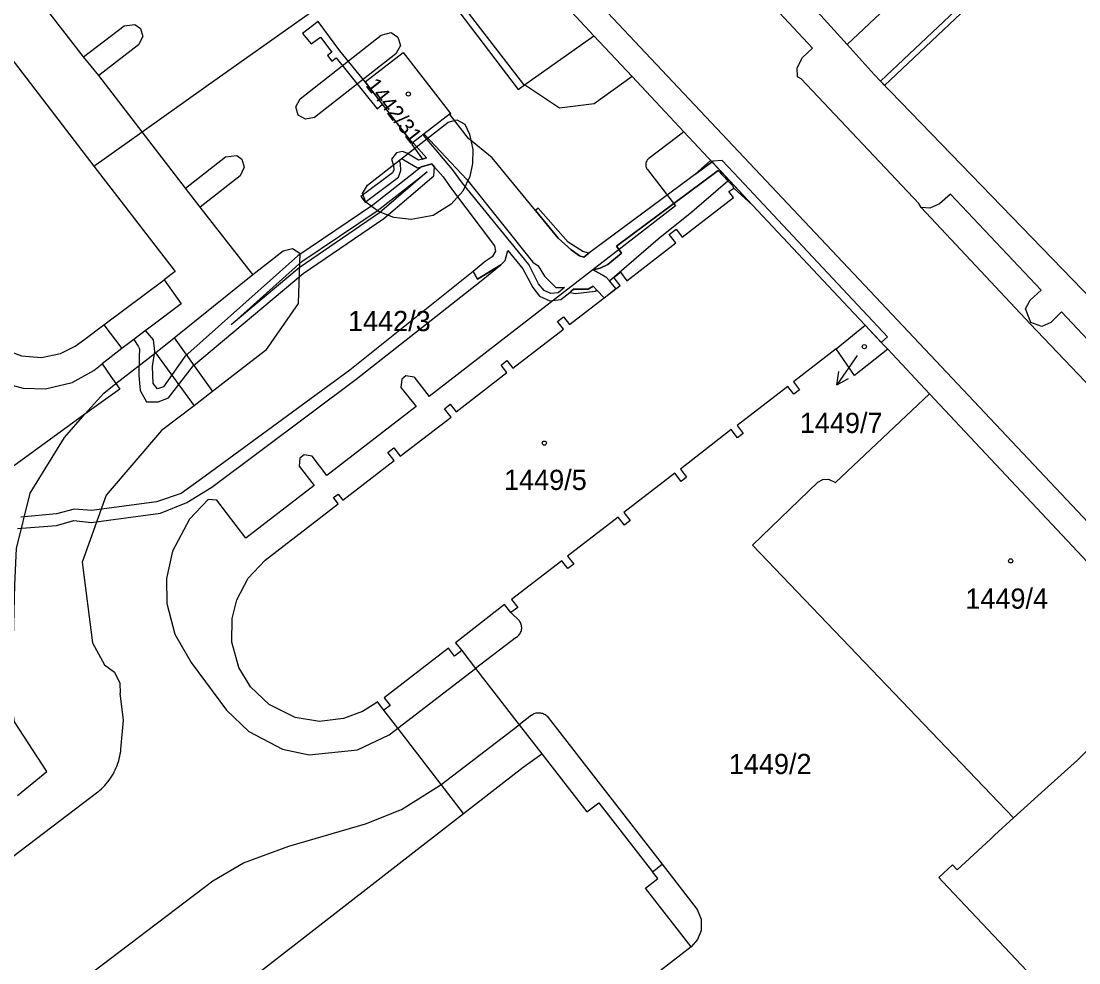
# Model space of a CAD drawing. Extents: x -821458 to -820266, y -1071458 to -1069826.
# Drawn here: x -821357.4 to -821268.4, y -1070486.3 to -1070407.2 of the extents above; entities that cross this region are included whole.
import ezdxf

# ---------------------------------------------------------------- set-up
doc = ezdxf.new("R2010")
doc.units = 0
for name, color, linetype in [('Vrstva 1', 7, 'Continuous'), ('Vrstva 13', 7, 'Continuous'), ('Vrstva 2', 7, 'Continuous'), ('Vrstva 4', 7, 'Continuous'), ('Vrstva 5', 7, 'Continuous'), ('Vrstva 7', 7, 'Continuous')]:
    doc.layers.add(name, color=color, linetype=linetype)

msp = doc.modelspace()

# ---------------------------------------------------------------- linework, layer by layer
at = {"layer": 'Vrstva 1'}
for p, q in [((-821293.71, -1070402.72), (-821287.92, -1070409.14)), ((-821288.83, -1070434.71), (-821286.39, -1070432.73)), ((-821280.98, -1070438.5), (-821284.5, -1070434.75)), ((-821260.09, -1070460.79), (-821280.98, -1070438.5))]:
    msp.add_line(p, q, dxfattribs=at)
for points in [[(-821309.21, -1070408.41), (-821319.78, -1070397.04), (-821333.24, -1070382.81), (-821356.7, -1070357.89), (-821358.08, -1070356.41), (-821363.03, -1070351.13), (-821378.93, -1070334.19)], [(-821285.11, -1070412.22), (-821269.17, -1070397.16), (-821271.43, -1070394.76)], [(-821272.9, -1070394.94), (-821276.13, -1070398.02), (-821276.59, -1070398.45), (-821278.3, -1070400.08), (-821278.45, -1070400.22), (-821284.67, -1070406.08), (-821287.92, -1070409.14)], [(-821351.25, -1070419.35), (-821347.19, -1070416.48), (-821341.82, -1070412.67), (-821325.37, -1070401), (-821323.53, -1070403.59), (-821322.96, -1070403.16), (-821315.57, -1070412.92), (-821315.04, -1070412.54), (-821309.21, -1070408.41)], [(-821360.92, -1070406.79), (-821351.25, -1070419.35)], [(-821295.86, -1070422.64), (-821301.64, -1070416.48), (-821305.99, -1070411.84), (-821309.21, -1070408.41)], [(-821328.45, -1070412.27), (-821325.25, -1070409.8), (-821321.27, -1070414.93), (-821324.45, -1070417.4), (-821328.45, -1070412.27)], [(-821287.92, -1070409.14), (-821285.64, -1070411.67), (-821285.11, -1070412.22)], [(-821183.73, -1070520.92), (-821205.46, -1070496.83), (-821215, -1070486.68), (-821216.61, -1070484.97), (-821257.56, -1070440.79), (-821261.33, -1070436.77), (-821285.11, -1070412.22)], [(-821394.98, -1070419.44), (-821390.24, -1070415.79), (-821375.82, -1070417.64), (-821362.5, -1070434.98), (-821361.14, -1070436.34), (-821359.22, -1070437.48), (-821357.18, -1070438.02), (-821355.31, -1070438.07), (-821353.07, -1070437.54), (-821351.25, -1070436.53), (-821350.55, -1070435.98)], [(-821350.55, -1070435.98), (-821349.81, -1070437.03), (-821349.39, -1070437.64), (-821349.07, -1070438.1), (-821352, -1070440.22), (-821360.71, -1070446.53), (-821360.94, -1070446.7), (-821361.48, -1070447.09), (-821368.87, -1070452.45), (-821370.62, -1070453.72), (-821370.9, -1070453.92), (-821370.95, -1070453.85), (-821375.3, -1070447.61), (-821390.16, -1070426.35), (-821392.14, -1070423.51), (-821394.98, -1070419.44)], [(-821351.25, -1070419.35), (-821344.42, -1070428.21), (-821345.35, -1070428.92), (-821343.92, -1070430.93), (-821348.9, -1070434.69), (-821350.55, -1070435.98)], [(-821326.86, -1070465.1), (-821327.39, -1070464.39), (-821327.53, -1070464.5), (-821328.67, -1070465.21), (-821330.25, -1070465.8), (-821332.28, -1070466.03), (-821334.32, -1070465.69), (-821336.5, -1070464.62), (-821338.07, -1070463.13), (-821339.05, -1070461.51), (-821339.64, -1070459.37), (-821339.62, -1070457.39), (-821339.24, -1070455.8), (-821338.28, -1070453.99), (-821336.85, -1070452.48), (-821330.71, -1070447.74), (-821331.11, -1070447.22), (-821330.71, -1070446.92), (-821330.31, -1070447.44), (-821326.01, -1070444.11), (-821326.53, -1070443.43), (-821326.02, -1070443.04), (-821325.49, -1070443.73), (-821321.22, -1070440.45), (-821321.76, -1070439.75), (-821321.28, -1070439.37), (-821320.78, -1070440.01), (-821316.52, -1070436.72), (-821317.01, -1070436.08), (-821316.52, -1070435.7), (-821316.03, -1070436.34), (-821311.76, -1070433.06), (-821312.26, -1070432.41), (-821311.76, -1070432.02), (-821311.25, -1070432.68), (-821307, -1070429.38), (-821307.52, -1070428.71), (-821306.98, -1070428.28), (-821306.43, -1070429), (-821302.32, -1070425.82), (-821302.87, -1070425.1), (-821302.28, -1070424.66), (-821301.77, -1070425.32), (-821297.46, -1070422), (-821297.85, -1070421.49), (-821297.44, -1070421.22), (-821295.86, -1070422.64)], [(-821286.39, -1070432.73), (-821287.8, -1070431.23), (-821295.86, -1070422.64)], [(-821284.5, -1070434.75), (-821284.77, -1070434.47), (-821286.39, -1070432.73)], [(-821288.83, -1070434.71), (-821292.43, -1070437.48), (-821291.91, -1070438.16), (-821292.39, -1070438.54), (-821292.91, -1070437.87), (-821297.17, -1070441.15), (-821296.65, -1070441.83), (-821297.13, -1070442.2), (-821297.66, -1070441.51), (-821301.93, -1070444.82), (-821301.41, -1070445.49), (-821301.88, -1070445.86), (-821302.41, -1070445.18), (-821306.68, -1070448.48), (-821306.16, -1070449.15), (-821306.64, -1070449.54), (-821307.17, -1070448.86), (-821311.42, -1070452.15), (-821310.9, -1070452.82), (-821311.39, -1070453.18), (-821311.89, -1070452.53), (-821316.12, -1070455.79), (-821315.61, -1070456.46), (-821316.2, -1070456.88), (-821316.72, -1070456.21), (-821320.83, -1070459.42), (-821320.32, -1070460.08), (-821320.92, -1070460.54), (-821321.44, -1070459.87), (-821326.83, -1070464.06), (-821326.33, -1070464.7), (-821326.86, -1070465.1)], [(-821284.5, -1070434.75), (-821287.28, -1070436.95), (-821288.83, -1070434.71)], [(-821273.93, -1070474.15), (-821295.87, -1070451.21), (-821290.38, -1070445.93), (-821289.95, -1070445.7), (-821289.47, -1070445.67), (-821288.88, -1070445.96), (-821280.98, -1070438.5)], [(-821260.09, -1070460.79), (-821268.54, -1070469.28), (-821271.57, -1070472.02), (-821273.93, -1070474.15)], [(-821320.16, -1070473.76), (-821322.04, -1070471.33), (-821325.7, -1070466.6), (-821326.86, -1070465.1)], [(-821320.16, -1070473.76), (-821315.16, -1070469.88), (-821313.58, -1070468.77), (-821309.79, -1070473.64), (-821308.8, -1070472.89), (-821304.29, -1070478.67), (-821303.47, -1070478.04), (-821300.52, -1070481.83), (-821300.18, -1070482.66), (-821300.19, -1070483.6), (-821300.49, -1070484.36), (-821301.04, -1070484.97), (-821304.49, -1070487.68), (-821307.43, -1070489.92), (-821331.64, -1070508.76), (-821336.37, -1070512.34), (-821340.055, -1070515.253)], [(-821351.742, -1070498.854), (-821351.38, -1070498.3), (-821349.56, -1070496.61), (-821343.56, -1070491.95), (-821320.16, -1070473.76)], [(-821273.93, -1070474.15), (-821275.52, -1070475.59), (-821275.85, -1070475.93), (-821278.67, -1070478.52), (-821279.06, -1070478.09), (-821280.19, -1070479.14), (-821279.86, -1070479.52), (-821275.13, -1070484.54), (-821270.46, -1070489.5), (-821261.8, -1070481.24)]]:
    msp.add_lwpolyline(points, dxfattribs=at)
at = {"layer": 'Vrstva 13'}
for points in [[(-821285.11, -1070412.22), (-821284.76, -1070412.58), (-821268.47, -1070397.18), (-821271.68, -1070393.78), (-821272.04, -1070394.12), (-821269.17, -1070397.16)], [(-821326.99, -1070414.14), (-821328.45, -1070412.27), (-821330.58, -1070409.67), (-821332.4, -1070407.19), (-821333.72, -1070408.2), (-821332.98, -1070409.07), (-821332.18, -1070408.51), (-821331.24, -1070409.79), (-821331.61, -1070410.07), (-821331.25, -1070410.55), (-821330.87, -1070410.27), (-821327.44, -1070414.54)], [(-821321.23, -1070414.98), (-821321.27, -1070414.93), (-821324.45, -1070417.4), (-821328.45, -1070412.27), (-821324.45, -1070417.48), (-821324.37, -1070417.42), (-821323.27, -1070418.67), (-821323.62, -1070418.77), (-821323.96, -1070418.87), (-821324.94, -1070418.28), (-821325.3, -1070418.13), (-821325.81, -1070418.25), (-821326.22, -1070418.78), (-821326.06, -1070419.3), (-821326.03, -1070419.66), (-821326.13, -1070419.91), (-821328.8, -1070421.92), (-821328.44, -1070422.4), (-821325.63, -1070420.29), (-821325.43, -1070419.74), (-821325.46, -1070419.18), (-821325.56, -1070418.9), (-821325.47, -1070418.79), (-821325.35, -1070418.76), (-821325.2, -1070418.82), (-821324.04, -1070419.51), (-821323.69, -1070419.41), (-821322.83, -1070419.17), (-821322.6, -1070419.44), (-821321.87, -1070420.27), (-821321.18, -1070421.27), (-821317.55, -1070426.05), (-821317.48, -1070426.51), (-821317.77, -1070426.98), (-821318.34, -1070427.37), (-821319.37, -1070428.22), (-821318.98, -1070428.86), (-821318.06, -1070428.31), (-821317.03, -1070427.67), (-821316.66, -1070427.28), (-821316.43, -1070426.44), (-821315.18, -1070427.98), (-821314.35, -1070429.57), (-821313.77, -1070430.3), (-821312.92, -1070430.69), (-821311.98, -1070430.58), (-821311.22, -1070429.97), (-821311.11, -1070429.88), (-821310.91, -1070429.69), (-821309.69, -1070429.7), (-821309.28, -1070429.46), (-821308.97, -1070429.78), (-821308.34, -1070430.42), (-821307.35, -1070429.65), (-821307.9, -1070429.01), (-821308.17, -1070428.68), (-821309.28, -1070428.07), (-821308.68, -1070427.94), (-821308.02, -1070427.62), (-821306.88, -1070426.68), (-821307.31, -1070426.1), (-821298.77, -1070419.73), (-821297.59, -1070420.97), (-821297.44, -1070421.22), (-821295.86, -1070422.64), (-821299.27, -1070419.01), (-821299.58, -1070419.21), (-821309.09, -1070426.27), (-821309.62, -1070426.68), (-821310.06, -1070427.02), (-821310.42, -1070426.9), (-821311.13, -1070426.4), (-821312.2, -1070425.42), (-821314.11, -1070423.1), (-821317.75, -1070418.65), (-821319.74, -1070417.03), (-821321.3, -1070415.04)], [(-821314.33, -1070427.44), (-821313.88, -1070427.73), (-821313.35, -1070428.61), (-821312.4, -1070429.57), (-821311.69, -1070429.57), (-821312.22, -1070430), (-821312.82, -1070430.07), (-821313.39, -1070429.82), (-821313.85, -1070429.25), (-821314.68, -1070427.64), (-821320.25, -1070420.78), (-821321.09, -1070419.64), (-821323.52, -1070416.76), (-821323.44, -1070416.7), (-821319.9, -1070420.49)], [(-821324.37, -1070417.42), (-821324.45, -1070417.48), (-821324.52, -1070417.53), (-821323.62, -1070418.77), (-821323.27, -1070418.67)], [(-821299.27, -1070419.01), (-821299.39, -1070418.88), (-821300.72, -1070420.06), (-821299.58, -1070419.21)], [(-821299.27, -1070419.01), (-821295.86, -1070422.64), (-821287.8, -1070431.23), (-821286.39, -1070432.73), (-821285.04, -1070434.18), (-821284.52, -1070433.7), (-821292.48, -1070425.21), (-821296.98, -1070420.41), (-821298.42, -1070418.89), (-821299.18, -1070418.95)], [(-821345.38, -1070437.9), (-821345.91, -1070438.09), (-821346.26, -1070437.63), (-821346.32, -1070436.2), (-821346.12, -1070434.94), (-821346.23, -1070433.97), (-821346.9, -1070433.18), (-821347.89, -1070433.93), (-821347.52, -1070434.49), (-821347.42, -1070434.73), (-821347.43, -1070435.36), (-821347.47, -1070436.95), (-821347.35, -1070438.23), (-821346.81, -1070439.17), (-821345.84, -1070439.17), (-821344.98, -1070438.83), (-821342.87, -1070436.13), (-821333.64, -1070428.39), (-821326.87, -1070423.77), (-821322.65, -1070420.17), (-821322.6, -1070419.44), (-821322.83, -1070419.17), (-821323.69, -1070419.41), (-821327.79, -1070422.64), (-821334.11, -1070426.89), (-821343.61, -1070435.37)], [(-821309.28, -1070428.07), (-821308.17, -1070428.68), (-821307.9, -1070429.01), (-821303.81, -1070425.46), (-821300.96, -1070423.2), (-821297.95, -1070420.59), (-821298.77, -1070419.73), (-821307.31, -1070426.1), (-821306.88, -1070426.68), (-821308.02, -1070427.62), (-821308.68, -1070427.94)], [(-821327.23, -1070423.29), (-821334, -1070427.91), (-821339.71, -1070432.69), (-821333.75, -1070427.37), (-821327.43, -1070423.12), (-821323.23, -1070419.85)], [(-821310.06, -1070427.02), (-821309.62, -1070426.68), (-821310.14, -1070426.54), (-821311.36, -1070425.76), (-821313.89, -1070422.88), (-821314.11, -1070423.1), (-821312.2, -1070425.42), (-821311.13, -1070426.4), (-821310.42, -1070426.9)], [(-821311.22, -1070429.97), (-821310.74, -1070430.06), (-821309.1, -1070429.87), (-821308.97, -1070429.78), (-821309.28, -1070429.46), (-821309.69, -1070429.7), (-821310.91, -1070429.69), (-821311.11, -1070429.88)]]:
    msp.add_lwpolyline(points, close=True, dxfattribs=at)
msp.add_lwpolyline([(-821357.66, -1070449.83), (-821354.4, -1070449.56), (-821352.92, -1070449.15), (-821351.47, -1070449.3), (-821345.64, -1070448.52), (-821343.44, -1070447.63), (-821341.32, -1070446.34), (-821329.2, -1070437.28), (-821318.67, -1070428.99), (-821317.03, -1070427.67), (-821318.98, -1070428.86), (-821319.37, -1070428.22), (-821329.74, -1070436.52), (-821341.88, -1070445.41), (-821343.91, -1070446.89), (-821345.97, -1070447.57), (-821351.41, -1070448.3), (-821352.9, -1070448.18), (-821354.4, -1070448.59), (-821357.39, -1070448.86)], dxfattribs=at)
at = {"layer": 'Vrstva 4'}
for p, q in [((-821352.11, -1070410.18), (-821359.45, -1070400.69)), ((-821290.82, -1070409.44), (-821298.28, -1070401.44)), ((-821350.84, -1070411.75), (-821352.11, -1070410.18)), ((-821347.19, -1070416.48), (-821350.84, -1070411.75)), ((-821343.54, -1070421.2), (-821347.19, -1070416.48)), ((-821302.25, -1070416.94), (-821304.59, -1070418.72)), ((-821301.64, -1070416.48), (-821302.25, -1070416.94)), ((-821304.71, -1070419.64), (-821302.35, -1070422.7)), ((-821342.3, -1070422.8), (-821343.54, -1070421.2)), ((-821337.88, -1070428.47), (-821342.3, -1070422.8)), ((-821302.35, -1070422.7), (-821323.07, -1070438.73)), ((-821344.5, -1070433.8), (-821337.88, -1070428.47)), ((-821350.41, -1070432.69), (-821345.35, -1070428.92)), ((-821352.02, -1070433.9), (-821350.41, -1070432.69)), ((-821350.41, -1070432.69), (-821348.9, -1070434.69)), ((-821346.06, -1070435.06), (-821344.5, -1070433.8)), ((-821344.5, -1070433.8), (-821341.26, -1070438.29)), ((-821349.39, -1070437.64), (-821346.06, -1070435.06)), ((-821346.06, -1070435.06), (-821342.82, -1070439.52)), ((-821325.36, -1070437.28), (-821325.43, -1070437.96)), ((-821325.01, -1070437), (-821325.36, -1070437.28)), ((-821324.32, -1070437.1), (-821325.01, -1070437)), ((-821324.32, -1070437.1), (-821323.07, -1070438.73)), ((-821341.26, -1070438.29), (-821342.82, -1070439.52)), ((-821325.43, -1070437.96), (-821324.15, -1070439.55)), ((-821324.15, -1070439.55), (-821331.66, -1070445.37)), ((-821333.56, -1070443.63), (-821333.92, -1070443.9)), ((-821332.9, -1070443.75), (-821333.56, -1070443.63)), ((-821331.66, -1070445.37), (-821332.9, -1070443.75)), ((-821333.92, -1070443.9), (-821334, -1070444.58)), ((-821334, -1070444.58), (-821332.73, -1070446.19)), ((-821332.73, -1070446.19), (-821338.47, -1070450.63)), ((-821341.63, -1070447.38), (-821343.21, -1070449.04)), ((-821340.92, -1070447.44), (-821341.63, -1070447.38)), ((-821338.47, -1070450.63), (-821340.92, -1070447.44)), ((-821343.21, -1070449.04), (-821344.64, -1070451.71)), ((-821344.64, -1070451.71), (-821345.14, -1070454.01)), ((-821345.14, -1070454.01), (-821345.12, -1070456.13)), ((-821345.12, -1070456.13), (-821344.45, -1070458.71)), ((-821315.47, -1070457.57), (-821316.2, -1070456.88)), ((-821344.45, -1070458.71), (-821343.07, -1070461.07)), ((-821351.36, -1070459.44), (-821350.36, -1070461.28)), ((-821315.7, -1070458.95), (-821319.15, -1070461.59)), ((-821320.32, -1070460.08), (-821319.15, -1070461.59)), ((-821343.07, -1070461.07), (-821340.1, -1070465.08)), ((-821325.7, -1070466.6), (-821319.15, -1070461.59)), ((-821319.15, -1070461.59), (-821315.49, -1070466.31)), ((-821348.76, -1070465.92), (-821349.05, -1070463.65)), ((-821340.1, -1070465.08), (-821338.23, -1070466.88)), ((-821348.97, -1070468.37), (-821348.76, -1070465.92)), ((-821314.44, -1070465.5), (-821315.49, -1070466.31)), ((-821313.05, -1070465.69), (-821303.47, -1070478.04)), ((-821338.23, -1070466.88), (-821335.38, -1070468.37)), ((-821326.42, -1070467.15), (-821325.7, -1070466.6)), ((-821322.04, -1070471.33), (-821315.49, -1070466.31)), ((-821315.49, -1070466.31), (-821313.58, -1070468.77)), ((-821329.09, -1070468.43), (-821326.42, -1070467.15)), ((-821335.38, -1070468.37), (-821333.15, -1070468.85)), ((-821333.15, -1070468.85), (-821329.09, -1070468.43)), ((-821322.21, -1070471.46), (-821322.04, -1070471.33)), ((-821350.92, -1070471.97), (-821361.45, -1070479.98)), ((-821325.37, -1070473.44), (-821322.21, -1070471.46)), ((-821328.4, -1070474.65), (-821325.37, -1070473.44)), ((-821334.86, -1070476.52), (-821328.4, -1070474.65)), ((-821338.66, -1070477.92), (-821334.86, -1070476.52)), ((-821341.25, -1070479.44), (-821338.66, -1070477.92)), ((-821304.86, -1070480.04), (-821303.84, -1070479.25)), ((-821303.84, -1070479.25), (-821304.29, -1070478.67)), ((-821354.34, -1070489.34), (-821341.25, -1070479.44)), ((-821301.04, -1070484.97), (-821304.86, -1070480.04))]:
    msp.add_line(p, q, dxfattribs=at)
for points in [[(-821354.82, -1070356.72), (-821348.41, -1070363.52), (-821328.79, -1070384.4), (-821304.41, -1070410.3), (-821282.75, -1070433.29), (-821254.81, -1070462.93)], [(-821315.04, -1070412.54), (-821315.09, -1070412.51), (-821357.05, -1070358.16), (-821356.7, -1070357.89)], [(-821352.11, -1070410.18), (-821348.71, -1070407.57), (-821347.79, -1070407.45), (-821347.33, -1070407.79), (-821347.13, -1070408.47), (-821347.5, -1070409.17), (-821350.84, -1070411.75)], [(-821333.89, -1070413.7), (-821327.09, -1070408.34), (-821326.26, -1070408.14), (-821325.68, -1070408.52), (-821325.48, -1070409.22), (-821325.85, -1070409.91), (-821332.69, -1070415.26), (-821333.45, -1070415.42), (-821334.06, -1070415.07), (-821334.26, -1070414.37), (-821333.89, -1070413.7)], [(-821292.11, -1070411.1), (-821291.67, -1070410.24), (-821290.82, -1070409.44)], [(-821281.7, -1070422.85), (-821281.88, -1070422.51), (-821291.78, -1070412.03), (-821292.08, -1070411.85), (-821292.11, -1070411.1)], [(-821305.99, -1070411.84), (-821309.18, -1070414.12), (-821312.11, -1070414.49), (-821315.04, -1070412.54)], [(-821396.41, -1070417.4), (-821391.83, -1070413.88), (-821373.58, -1070416.24), (-821360.52, -1070433.51), (-821358.97, -1070434.7), (-821357.33, -1070435.3), (-821355.66, -1070435.44), (-821354.06, -1070435.12), (-821352.81, -1070434.49), (-821352.02, -1070433.9)], [(-821328.24, -1070420.97), (-821321.45, -1070415.66), (-821320.72, -1070415.46), (-821320.06, -1070415.84), (-821319.67, -1070416.68), (-821319.39, -1070417.97), (-821319.4, -1070419.15), (-821319.63, -1070420.22), (-821320.22, -1070421.46), (-821321.2, -1070422.56), (-821322.72, -1070423.51), (-821324.56, -1070423.85), (-821326.03, -1070423.69), (-821327.32, -1070423.18), (-821328.38, -1070422.38), (-821328.65, -1070421.66), (-821328.24, -1070420.97)], [(-821343.54, -1070421.2), (-821340.19, -1070418.58), (-821339.23, -1070418.47), (-821338.8, -1070418.77), (-821338.6, -1070419.46), (-821338.96, -1070420.17), (-821342.3, -1070422.8)], [(-821304.59, -1070418.72), (-821304.642, -1070418.764), (-821304.69, -1070418.814), (-821304.732, -1070418.869), (-821304.768, -1070418.927), (-821304.798, -1070418.989), (-821304.821, -1070419.054), (-821304.837, -1070419.121), (-821304.846, -1070419.189), (-821304.847, -1070419.258), (-821304.842, -1070419.326), (-821304.829, -1070419.394), (-821304.809, -1070419.46), (-821304.783, -1070419.523), (-821304.749, -1070419.584), (-821304.71, -1070419.64)], [(-821263.32, -1070442.26), (-821263.66, -1070441.37), (-821263.26, -1070440.44), (-821262.34, -1070439.62), (-821269.88, -1070431.62), (-821270.79, -1070432.49), (-821271.53, -1070432.83), (-821272.47, -1070432.49), (-821272.91, -1070431.35), (-821272.53, -1070430.62), (-821271.61, -1070429.79), (-821279.23, -1070421.71), (-821280.16, -1070422.54), (-821280.95, -1070422.88), (-821281.7, -1070422.85)], [(-821263.32, -1070442.26), (-821272.51, -1070432.62), (-821281.7, -1070422.85)], [(-821337.88, -1070428.47), (-821335.32, -1070426.49), (-821334.56, -1070426.27), (-821333.92, -1070426.68), (-821334.08, -1070430.91), (-821336.82, -1070434.85), (-821341.26, -1070438.29)], [(-821352, -1070440.22), (-821350.4, -1070438.43), (-821349.39, -1070437.64)], [(-821357.91, -1070466.06), (-821358.14, -1070464.56), (-821357.9, -1070454.54), (-821357.75, -1070451.5), (-821356.59, -1070446.86), (-821353.73, -1070442.16), (-821352, -1070440.22)], [(-821342.82, -1070439.52), (-821345.55, -1070441.57), (-821350.22, -1070447.02), (-821352.24, -1070452.64), (-821351.36, -1070459.44)], [(-821315.7, -1070458.95), (-821315.63, -1070458.898), (-821315.565, -1070458.84), (-821315.506, -1070458.777), (-821315.452, -1070458.708), (-821315.405, -1070458.635), (-821315.365, -1070458.558), (-821315.332, -1070458.478), (-821315.306, -1070458.395), (-821315.288, -1070458.309), (-821315.278, -1070458.223), (-821315.275, -1070458.136), (-821315.28, -1070458.049), (-821315.294, -1070457.963), (-821315.314, -1070457.879), (-821315.343, -1070457.797), (-821315.378, -1070457.717), (-821315.421, -1070457.642), (-821315.47, -1070457.57)], [(-821350.36, -1070461.28), (-821349.52, -1070461.89), (-821349.06, -1070462.83), (-821349.05, -1070463.65)], [(-821314.44, -1070465.5), (-821314.369, -1070465.451), (-821314.293, -1070465.409), (-821314.215, -1070465.373), (-821314.133, -1070465.345), (-821314.05, -1070465.323), (-821313.965, -1070465.309), (-821313.878, -1070465.302), (-821313.792, -1070465.303), (-821313.706, -1070465.311), (-821313.621, -1070465.326), (-821313.538, -1070465.349), (-821313.457, -1070465.378), (-821313.379, -1070465.415), (-821313.304, -1070465.458), (-821313.233, -1070465.508), (-821313.167, -1070465.563), (-821313.106, -1070465.624), (-821313.05, -1070465.69)], [(-821357.67, -1070472.25), (-821355.21, -1070470.24), (-821357.91, -1070466.06)], [(-821350.92, -1070471.97), (-821350.766, -1070471.842), (-821350.617, -1070471.709), (-821350.473, -1070471.569), (-821350.334, -1070471.425), (-821350.201, -1070471.275), (-821350.074, -1070471.12), (-821349.953, -1070470.961), (-821349.838, -1070470.796), (-821349.73, -1070470.628), (-821349.628, -1070470.456), (-821349.532, -1070470.28), (-821349.444, -1070470.1), (-821349.362, -1070469.917), (-821349.287, -1070469.731), (-821349.22, -1070469.543), (-821349.16, -1070469.352), (-821349.107, -1070469.159), (-821349.061, -1070468.964), (-821349.023, -1070468.767), (-821348.993, -1070468.569), (-821348.97, -1070468.37)]]:
    msp.add_lwpolyline(points, dxfattribs=at)
at = {"layer": 'Vrstva 5'}
for centre in [(-821324.807, -1070413.299), (-821286.467, -1070434.539), (-821313.377, -1070442.639), (-821274.157, -1070452.539)]:
    msp.add_circle(centre, 0.175, dxfattribs=at)
at = {"layer": 'Vrstva 7'}
for p, q in [((-821287.06, -1070435.28), (-821288.781, -1070437.738)), ((-821288.781, -1070437.738), (-821288.617, -1070436.631)), ((-821288.781, -1070437.738), (-821287.797, -1070437.205))]:
    msp.add_line(p, q, dxfattribs=at)

# ---------------------------------------------------------------- texts
at = {"layer": 'Vrstva 2'}
msp.add_text('1442/31', height=1.304, rotation=308, dxfattribs=at).set_placement((-821328.456, -1070412.591))
for s, p in [('1442/3', (-821329.88, -1070433.229)), ('1449/7', (-821291.891, -1070441.793)), ('1449/5', (-821316.76, -1070446.58)), ('1449/4', (-821277.975, -1070456.56)), ('1449/2', (-821297.86, -1070470.46))]:
    msp.add_text(s, height=1.7, dxfattribs=at).set_placement(p)

doc.saveas('drawing.dxf')
